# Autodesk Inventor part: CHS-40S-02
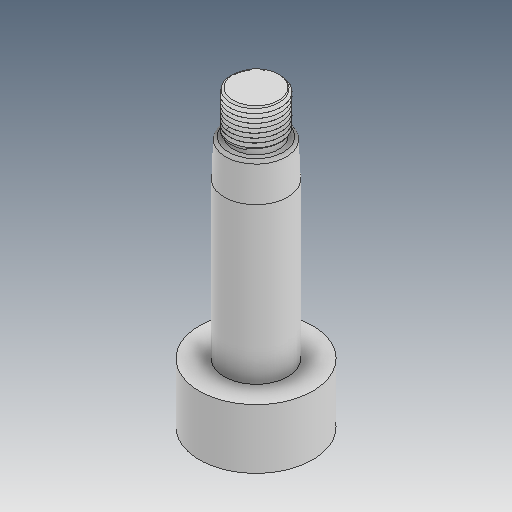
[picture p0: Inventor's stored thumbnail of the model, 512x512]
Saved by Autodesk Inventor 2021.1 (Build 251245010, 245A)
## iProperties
Created: 2019-04
Part Number: CHS-40S-02
Material: Ogólny
Document SubType Name: Modeling
Designer: user
Density: 1 g/cm^3
Appearance: Domyślna
Author: user
Revision Number: ÈÎºÎ
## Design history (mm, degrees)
feature "ÊäÈë1"
feature "ÊäÈë2"
node "Bryła1"
node "Bryła2"
